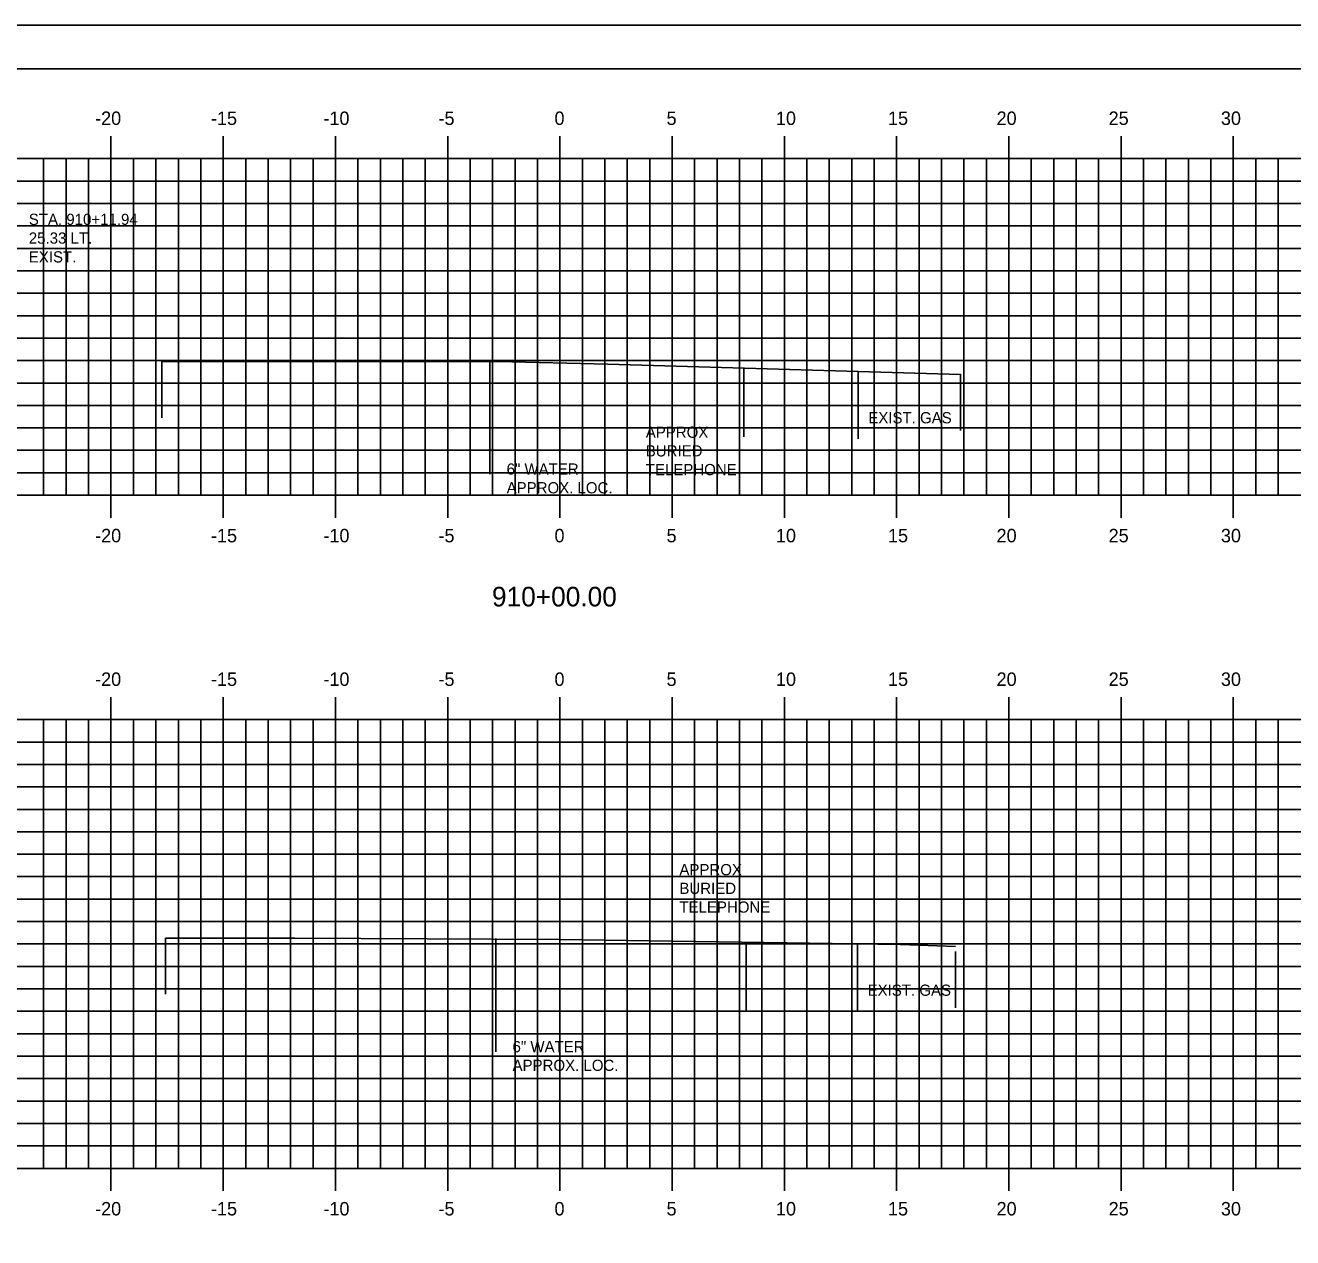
# Model space of a CAD drawing. Extents: x 1026799 to 1026969, y 394697 to 394807.
# Drawn here: x 1026858.5 to 1026915, y 394752.5 to 394806.5 of the extents above; entities that cross this region are included whole.
import ezdxf

# ---------------------------------------------------------------- set-up
doc = ezdxf.new("R2010")
doc.units = 0
for name, color, linetype in [('BORDER', 7, 'Continuous'), ('D_Text_Monospaced', 7, 'Continuous'), ('H_V ANNOTATION', 7, 'Continuous'), ('MAJOR', 7, 'Continuous'), ('MINOR', 7, 'Continuous'), ('PLOT BOUNDARY', 7, 'Continuous'), ('S_Roadway_Centerline', 7, 'Continuous'), ('S_Roadway_Edge_Pavement', 7, 'Continuous'), ('S_Utilities_UG_Gas_Line', 7, 'Continuous'), ('S_Utilities_UG_Telephone', 7, 'Continuous'), ('S_Utilities_UG_Water_Line', 7, 'Continuous')]:
    doc.layers.add(name, color=color, linetype=linetype)

msp = doc.modelspace()

# ---------------------------------------------------------------- linework, layer by layer
at = {"layer": 'BORDER'}
msp.add_line((1026967.348, 394804.607), (1026807.348, 394804.607), dxfattribs=at)
at = {"layer": 'MAJOR'}
for p, q in [((1026862.348, 394801.609), (1026862.348, 394800.607)), ((1026867.348, 394801.609), (1026867.348, 394800.607)), ((1026872.348, 394801.609), (1026872.348, 394800.607)), ((1026877.348, 394801.609), (1026877.348, 394800.607)), ((1026882.348, 394801.609), (1026882.348, 394800.607)), ((1026887.348, 394801.609), (1026887.348, 394800.607)), ((1026892.348, 394801.609), (1026892.348, 394800.607)), ((1026897.348, 394801.609), (1026897.348, 394800.607)), ((1026902.348, 394801.609), (1026902.348, 394800.607)), ((1026907.348, 394801.609), (1026907.348, 394800.607)), ((1026912.348, 394801.609), (1026912.348, 394800.607)), ((1026812.348, 394800.607), (1026952.348, 394800.607)), ((1026862.348, 394785.607), (1026862.348, 394800.607)), ((1026867.348, 394785.607), (1026867.348, 394800.607)), ((1026872.348, 394785.607), (1026872.348, 394800.607)), ((1026877.348, 394785.607), (1026877.348, 394800.607)), ((1026882.348, 394785.607), (1026882.348, 394800.607)), ((1026887.348, 394785.607), (1026887.348, 394800.607)), ((1026892.348, 394785.607), (1026892.348, 394800.607)), ((1026897.348, 394785.607), (1026897.348, 394800.607)), ((1026902.348, 394785.607), (1026902.348, 394800.607)), ((1026907.348, 394785.607), (1026907.348, 394800.607)), ((1026912.348, 394785.607), (1026912.348, 394800.607)), ((1026812.348, 394795.607), (1026952.348, 394795.607)), ((1026812.348, 394790.607), (1026952.348, 394790.607)), ((1026812.348, 394785.607), (1026952.348, 394785.607)), ((1026862.348, 394784.605), (1026862.348, 394785.607)), ((1026867.348, 394784.605), (1026867.348, 394785.607)), ((1026872.348, 394784.605), (1026872.348, 394785.607)), ((1026877.348, 394784.605), (1026877.348, 394785.607)), ((1026882.348, 394784.605), (1026882.348, 394785.607)), ((1026887.348, 394784.605), (1026887.348, 394785.607)), ((1026892.348, 394784.605), (1026892.348, 394785.607)), ((1026897.348, 394784.605), (1026897.348, 394785.607)), ((1026902.348, 394784.605), (1026902.348, 394785.607)), ((1026907.348, 394784.605), (1026907.348, 394785.607)), ((1026912.348, 394784.605), (1026912.348, 394785.607)), ((1026862.348, 394776.609), (1026862.348, 394775.607)), ((1026867.348, 394776.609), (1026867.348, 394775.607)), ((1026872.348, 394776.609), (1026872.348, 394775.607)), ((1026877.348, 394776.609), (1026877.348, 394775.607)), ((1026882.348, 394776.609), (1026882.348, 394775.607)), ((1026887.348, 394776.609), (1026887.348, 394775.607)), ((1026892.348, 394776.609), (1026892.348, 394775.607)), ((1026897.348, 394776.609), (1026897.348, 394775.607)), ((1026902.348, 394776.609), (1026902.348, 394775.607)), ((1026907.348, 394776.609), (1026907.348, 394775.607)), ((1026912.348, 394776.609), (1026912.348, 394775.607)), ((1026812.348, 394775.607), (1026952.348, 394775.607)), ((1026862.348, 394755.607), (1026862.348, 394775.607)), ((1026867.348, 394755.607), (1026867.348, 394775.607)), ((1026872.348, 394755.607), (1026872.348, 394775.607)), ((1026877.348, 394755.607), (1026877.348, 394775.607)), ((1026882.348, 394755.607), (1026882.348, 394775.607)), ((1026887.348, 394755.607), (1026887.348, 394775.607)), ((1026892.348, 394755.607), (1026892.348, 394775.607)), ((1026897.348, 394755.607), (1026897.348, 394775.607)), ((1026902.348, 394755.607), (1026902.348, 394775.607)), ((1026907.348, 394755.607), (1026907.348, 394775.607)), ((1026912.348, 394755.607), (1026912.348, 394775.607)), ((1026812.348, 394770.607), (1026952.348, 394770.607)), ((1026812.348, 394765.607), (1026952.348, 394765.607)), ((1026812.348, 394760.607), (1026952.348, 394760.607)), ((1026812.348, 394755.607), (1026952.348, 394755.607)), ((1026862.348, 394754.605), (1026862.348, 394755.607)), ((1026867.348, 394754.605), (1026867.348, 394755.607)), ((1026872.348, 394754.605), (1026872.348, 394755.607)), ((1026877.348, 394754.605), (1026877.348, 394755.607)), ((1026882.348, 394754.605), (1026882.348, 394755.607)), ((1026887.348, 394754.605), (1026887.348, 394755.607)), ((1026892.348, 394754.605), (1026892.348, 394755.607)), ((1026897.348, 394754.605), (1026897.348, 394755.607)), ((1026902.348, 394754.605), (1026902.348, 394755.607)), ((1026907.348, 394754.605), (1026907.348, 394755.607)), ((1026912.348, 394754.605), (1026912.348, 394755.607))]:
    msp.add_line(p, q, dxfattribs=at)
at = {"layer": 'MINOR'}
for p, q in [((1026859.348, 394785.607), (1026859.348, 394800.607)), ((1026860.348, 394785.607), (1026860.348, 394800.607)), ((1026861.348, 394785.607), (1026861.348, 394800.607)), ((1026863.348, 394785.607), (1026863.348, 394800.607)), ((1026864.348, 394785.607), (1026864.348, 394800.607)), ((1026865.348, 394785.607), (1026865.348, 394800.607)), ((1026866.348, 394785.607), (1026866.348, 394800.607)), ((1026868.348, 394785.607), (1026868.348, 394800.607)), ((1026869.348, 394785.607), (1026869.348, 394800.607)), ((1026870.348, 394785.607), (1026870.348, 394800.607)), ((1026871.348, 394785.607), (1026871.348, 394800.607)), ((1026873.348, 394785.607), (1026873.348, 394800.607)), ((1026874.348, 394785.607), (1026874.348, 394800.607)), ((1026875.348, 394785.607), (1026875.348, 394800.607)), ((1026876.348, 394785.607), (1026876.348, 394800.607)), ((1026878.348, 394785.607), (1026878.348, 394800.607)), ((1026879.348, 394785.607), (1026879.348, 394800.607)), ((1026880.348, 394785.607), (1026880.348, 394800.607)), ((1026881.348, 394785.607), (1026881.348, 394800.607)), ((1026883.348, 394785.607), (1026883.348, 394800.607)), ((1026884.348, 394785.607), (1026884.348, 394800.607)), ((1026885.348, 394785.607), (1026885.348, 394800.607)), ((1026886.348, 394785.607), (1026886.348, 394800.607)), ((1026888.348, 394785.607), (1026888.348, 394800.607)), ((1026889.348, 394785.607), (1026889.348, 394800.607)), ((1026890.348, 394785.607), (1026890.348, 394800.607)), ((1026891.348, 394785.607), (1026891.348, 394800.607)), ((1026893.348, 394785.607), (1026893.348, 394800.607)), ((1026894.348, 394785.607), (1026894.348, 394800.607)), ((1026895.348, 394785.607), (1026895.348, 394800.607)), ((1026896.348, 394785.607), (1026896.348, 394800.607)), ((1026898.348, 394785.607), (1026898.348, 394800.607)), ((1026899.348, 394785.607), (1026899.348, 394800.607)), ((1026900.348, 394785.607), (1026900.348, 394800.607)), ((1026901.348, 394785.607), (1026901.348, 394800.607)), ((1026903.348, 394785.607), (1026903.348, 394800.607)), ((1026904.348, 394785.607), (1026904.348, 394800.607)), ((1026905.348, 394785.607), (1026905.348, 394800.607)), ((1026906.348, 394785.607), (1026906.348, 394800.607)), ((1026908.348, 394785.607), (1026908.348, 394800.607)), ((1026909.348, 394785.607), (1026909.348, 394800.607)), ((1026910.348, 394785.607), (1026910.348, 394800.607)), ((1026911.348, 394785.607), (1026911.348, 394800.607)), ((1026913.348, 394785.607), (1026913.348, 394800.607)), ((1026914.348, 394785.607), (1026914.348, 394800.607)), ((1026812.348, 394799.607), (1026952.348, 394799.607)), ((1026812.348, 394798.607), (1026952.348, 394798.607)), ((1026812.348, 394797.607), (1026952.348, 394797.607)), ((1026812.348, 394796.607), (1026952.348, 394796.607)), ((1026812.348, 394794.607), (1026952.348, 394794.607)), ((1026812.348, 394793.607), (1026952.348, 394793.607)), ((1026812.348, 394792.607), (1026952.348, 394792.607)), ((1026812.348, 394791.607), (1026952.348, 394791.607)), ((1026812.348, 394789.607), (1026952.348, 394789.607)), ((1026812.348, 394788.607), (1026952.348, 394788.607)), ((1026812.348, 394787.607), (1026952.348, 394787.607)), ((1026812.348, 394786.607), (1026952.348, 394786.607)), ((1026859.348, 394755.607), (1026859.348, 394775.607)), ((1026860.348, 394755.607), (1026860.348, 394775.607)), ((1026861.348, 394755.607), (1026861.348, 394775.607)), ((1026863.348, 394755.607), (1026863.348, 394775.607)), ((1026864.348, 394755.607), (1026864.348, 394775.607)), ((1026865.348, 394755.607), (1026865.348, 394775.607)), ((1026866.348, 394755.607), (1026866.348, 394775.607)), ((1026868.348, 394755.607), (1026868.348, 394775.607)), ((1026869.348, 394755.607), (1026869.348, 394775.607)), ((1026870.348, 394755.607), (1026870.348, 394775.607)), ((1026871.348, 394755.607), (1026871.348, 394775.607)), ((1026873.348, 394755.607), (1026873.348, 394775.607)), ((1026874.348, 394755.607), (1026874.348, 394775.607)), ((1026875.348, 394755.607), (1026875.348, 394775.607)), ((1026876.348, 394755.607), (1026876.348, 394775.607)), ((1026878.348, 394755.607), (1026878.348, 394775.607)), ((1026879.348, 394755.607), (1026879.348, 394775.607)), ((1026880.348, 394755.607), (1026880.348, 394775.607)), ((1026881.348, 394755.607), (1026881.348, 394775.607)), ((1026883.348, 394755.607), (1026883.348, 394775.607)), ((1026884.348, 394755.607), (1026884.348, 394775.607)), ((1026885.348, 394755.607), (1026885.348, 394775.607)), ((1026886.348, 394755.607), (1026886.348, 394775.607)), ((1026888.348, 394755.607), (1026888.348, 394775.607)), ((1026889.348, 394755.607), (1026889.348, 394775.607)), ((1026890.348, 394755.607), (1026890.348, 394775.607)), ((1026891.348, 394755.607), (1026891.348, 394775.607)), ((1026893.348, 394755.607), (1026893.348, 394775.607)), ((1026894.348, 394755.607), (1026894.348, 394775.607)), ((1026895.348, 394755.607), (1026895.348, 394775.607)), ((1026896.348, 394755.607), (1026896.348, 394775.607)), ((1026898.348, 394755.607), (1026898.348, 394775.607)), ((1026899.348, 394755.607), (1026899.348, 394775.607)), ((1026900.348, 394755.607), (1026900.348, 394775.607)), ((1026901.348, 394755.607), (1026901.348, 394775.607)), ((1026903.348, 394755.607), (1026903.348, 394775.607)), ((1026904.348, 394755.607), (1026904.348, 394775.607)), ((1026905.348, 394755.607), (1026905.348, 394775.607)), ((1026906.348, 394755.607), (1026906.348, 394775.607)), ((1026908.348, 394755.607), (1026908.348, 394775.607)), ((1026909.348, 394755.607), (1026909.348, 394775.607)), ((1026910.348, 394755.607), (1026910.348, 394775.607)), ((1026911.348, 394755.607), (1026911.348, 394775.607)), ((1026913.348, 394755.607), (1026913.348, 394775.607)), ((1026914.348, 394755.607), (1026914.348, 394775.607)), ((1026812.348, 394774.607), (1026952.348, 394774.607)), ((1026812.348, 394773.607), (1026952.348, 394773.607)), ((1026812.348, 394772.607), (1026952.348, 394772.607)), ((1026812.348, 394771.607), (1026952.348, 394771.607)), ((1026812.348, 394769.607), (1026952.348, 394769.607)), ((1026812.348, 394768.607), (1026952.348, 394768.607)), ((1026812.348, 394767.607), (1026952.348, 394767.607)), ((1026812.348, 394766.607), (1026952.348, 394766.607)), ((1026812.348, 394764.607), (1026952.348, 394764.607)), ((1026812.348, 394763.607), (1026952.348, 394763.607)), ((1026812.348, 394762.607), (1026952.348, 394762.607)), ((1026812.348, 394761.607), (1026952.348, 394761.607)), ((1026812.348, 394759.607), (1026952.348, 394759.607)), ((1026812.348, 394758.607), (1026952.348, 394758.607)), ((1026812.348, 394757.607), (1026952.348, 394757.607)), ((1026812.348, 394756.607), (1026952.348, 394756.607))]:
    msp.add_line(p, q, dxfattribs=at)
at = {"layer": 'PLOT BOUNDARY'}
msp.add_lwpolyline([(1026799.254, 394696.548), (1026969.254, 394696.548), (1026969.254, 394806.548), (1026799.254, 394806.548)], close=True, dxfattribs=at)
at = {"layer": 'S_Roadway_Centerline'}
for points in [[(1026864.616, 394791.559), (1026865.207, 394791.57), (1026876.149, 394791.563), (1026877.749, 394791.566), (1026878.759, 394791.563), (1026879.398, 394791.561), (1026879.603, 394791.56), (1026884.476, 394791.444), (1026900.192, 394790.986), (1026900.193, 394791.006)], [(1026864.771, 394765.865), (1026870.542, 394765.862), (1026882.328, 394765.808), (1026897.515, 394765.589), (1026899.967, 394765.491)]]:
    msp.add_lwpolyline(points, dxfattribs=at)
at = {"layer": 'S_Roadway_Edge_Pavement'}
for p, q in [((1026864.616, 394791.559), (1026864.616, 394789.059)), ((1026900.192, 394790.986), (1026900.192, 394788.486)), ((1026864.771, 394765.865), (1026864.771, 394763.365)), ((1026899.967, 394765.267), (1026899.967, 394762.767))]:
    msp.add_line(p, q, dxfattribs=at)
at = {"layer": 'S_Utilities_UG_Gas_Line'}
for p, q in [((1026895.64, 394791.118), (1026895.64, 394788.118)), ((1026895.609, 394765.607), (1026895.609, 394762.607))]:
    msp.add_line(p, q, dxfattribs=at)
at = {"layer": 'S_Utilities_UG_Telephone'}
for p, q in [((1026879.226, 394791.606), (1026879.226, 394788.606)), ((1026879.49, 394765.849), (1026879.49, 394762.849))]:
    msp.add_line(p, q, dxfattribs=at)
at = {"layer": 'S_Utilities_UG_Water_Line'}
for p, q in [((1026879.226, 394791.543), (1026879.226, 394786.543)), ((1026890.548, 394791.267), (1026890.548, 394788.213)), ((1026879.49, 394765.802), (1026879.49, 394760.802)), ((1026890.648, 394765.688), (1026890.648, 394762.635))]:
    msp.add_line(p, q, dxfattribs=at)

# ---------------------------------------------------------------- texts
at = {"layer": 'D_Text_Monospaced'}
for s, height, p in [('STA. 910+11.94', 0.49998, (1026858.686, 394797.652)), ('25.33 LT.', 0.5, (1026858.686, 394796.818)), ('EXIST. ', 0.5, (1026858.686, 394795.978)), ('EXIST. GAS', 0.5, (1026896.087, 394788.809)), ('APPROX', 0.5, (1026886.173, 394788.166)), ('BURIED ', 0.5, (1026886.173, 394787.333)), ('6" WATER', 0.5, (1026879.974, 394786.522)), ('TELEPHONE', 0.5, (1026886.173, 394786.499)), ('APPROX. LOC.', 0.49998, (1026879.974, 394785.689)), ('APPROX', 0.5, (1026887.671, 394768.669)), ('BURIED ', 0.5, (1026887.671, 394767.836)), ('TELEPHONE', 0.5, (1026887.671, 394767.003)), ('EXIST. GAS', 0.5, (1026896.056, 394763.297)), ('6" WATER', 0.5, (1026880.238, 394760.782)), ('APPROX. LOC.', 0.49998, (1026880.238, 394759.949))]:
    msp.add_text(s, height=height, dxfattribs=at).set_placement(p)
at = {"layer": 'H_V ANNOTATION'}
for s, height, p in [('-20', 0.6, (1026861.641, 394802.107)), ('-15', 0.6, (1026866.804, 394802.107)), ('-10', 0.6, (1026871.812, 394802.107)), ('-5', 0.6, (1026876.938, 394802.107)), ('0', 0.6, (1026882.107, 394802.107)), ('5', 0.6, (1026887.099, 394802.107)), ('10', 0.6, (1026891.973, 394802.107)), ('15', 0.6, (1026896.965, 394802.107)), ('20', 0.6, (1026901.802, 394802.107)), ('25', 0.6, (1026906.794, 394802.107)), ('30', 0.6, (1026911.796, 394802.107)), ('-20', 0.6, (1026861.641, 394783.507)), ('-15', 0.6, (1026866.804, 394783.507)), ('-10', 0.6, (1026871.812, 394783.507)), ('-5', 0.6, (1026876.938, 394783.507)), ('0', 0.6, (1026882.107, 394783.507)), ('5', 0.6, (1026887.099, 394783.507)), ('10', 0.6, (1026891.973, 394783.507)), ('15', 0.6, (1026896.965, 394783.507)), ('20', 0.6, (1026901.802, 394783.507)), ('25', 0.6, (1026906.794, 394783.507)), ('30', 0.6, (1026911.796, 394783.507)), ('910+00.00', 0.875, (1026879.32, 394780.65)), ('-20', 0.6, (1026861.641, 394777.107)), ('-15', 0.6, (1026866.804, 394777.107)), ('-10', 0.6, (1026871.812, 394777.107)), ('-5', 0.6, (1026876.938, 394777.107)), ('0', 0.6, (1026882.107, 394777.107)), ('5', 0.6, (1026887.099, 394777.107)), ('10', 0.6, (1026891.973, 394777.107)), ('15', 0.6, (1026896.965, 394777.107)), ('20', 0.6, (1026901.802, 394777.107)), ('25', 0.6, (1026906.794, 394777.107)), ('30', 0.6, (1026911.796, 394777.107)), ('-20', 0.6, (1026861.641, 394753.507)), ('-15', 0.6, (1026866.804, 394753.507)), ('-10', 0.6, (1026871.812, 394753.507)), ('-5', 0.6, (1026876.938, 394753.507)), ('0', 0.6, (1026882.107, 394753.507)), ('5', 0.6, (1026887.099, 394753.507)), ('10', 0.6, (1026891.973, 394753.507)), ('15', 0.6, (1026896.965, 394753.507)), ('20', 0.6, (1026901.802, 394753.507)), ('25', 0.6, (1026906.794, 394753.507)), ('30', 0.6, (1026911.796, 394753.507))]:
    msp.add_text(s, height=height, dxfattribs=at).set_placement(p)
at = {"layer": 'S_Roadway_Centerline'}
for s, p in [('L', (1026882.319, 394765.801)), ('C', (1026882.322, 394765.808))]:
    msp.add_text(s, height=0.0146, dxfattribs=at).set_placement(p)

doc.saveas('drawing.dxf')
